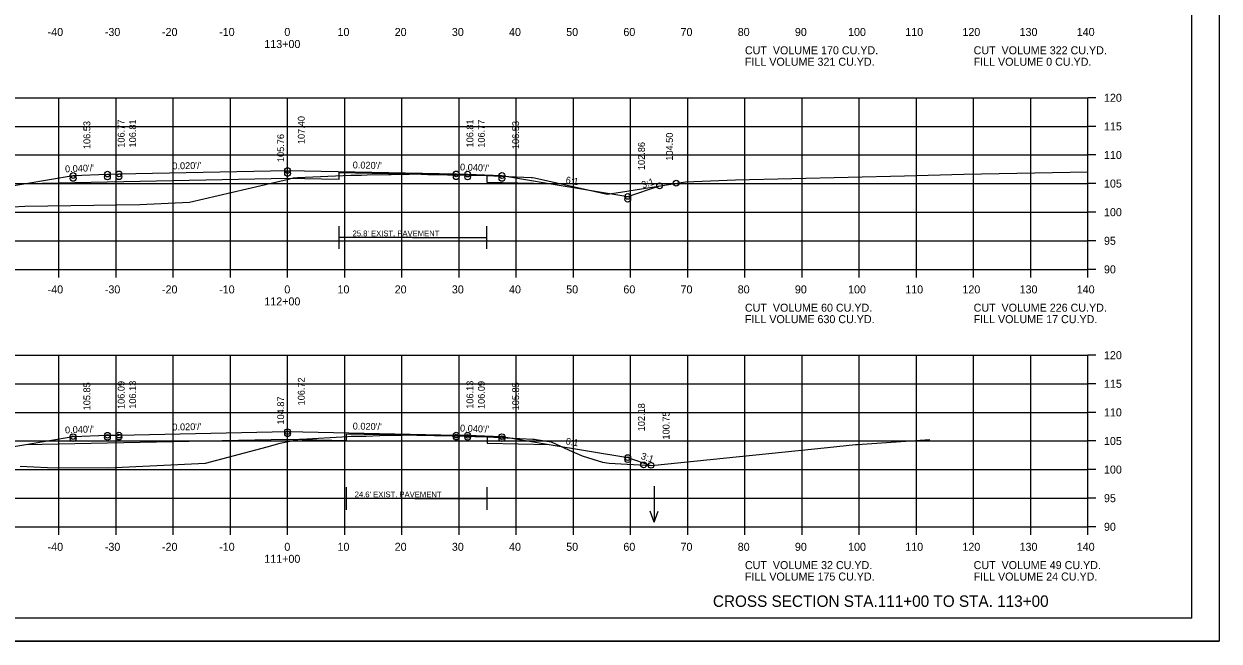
# Model space of a CAD drawing. Extents: x 1175611 to 1176402, y -433344 to -416213.
# Drawn here: x 1175734.9 to 1175943.9, y -432490.2 to -432382.3 of the extents above; entities that cross this region are included whole.
import ezdxf

# ---------------------------------------------------------------- set-up
doc = ezdxf.new("R2010")
doc.units = 0
for name, color, linetype in [('Default', 7, 'Continuous'), ('R_Alt Surface', 7, 'Continuous'), ('R_Axis', 7, 'Continuous'), ('R_Axis Annot', 7, 'Continuous'), ('R_Border', 7, 'Continuous'), ('R_Draft', 7, 'Continuous'), ('R_Exist Surface', 7, 'Continuous'), ('R_Fin Surface', 7, 'Continuous'), ('R_Grid', 7, 'Continuous'), ('R_No Plot', 7, 'Continuous'), ('R_Water Annot', 7, 'Continuous'), ('R_Xsect Elev', 7, 'Continuous'), ('R_Xsect Slope', 7, 'Continuous')]:
    doc.layers.add(name, color=color, linetype=linetype)

msp = doc.modelspace()

# ---------------------------------------------------------------- linework, layer by layer
at = {"layer": 'R_Alt Surface'}
for points in [[(1175735.2, -432410.17), (1175749.47, -432409.88), (1175780.97, -432409.25), (1175790.01, -432409.43), (1175790.01, -432408.26), (1175815.83, -432408.78), (1175815.83, -432409.95), (1175826.75, -432410.17)], [(1175735.2, -432455.81), (1175749.47, -432455.53), (1175780.97, -432454.9), (1175791.29, -432455.11), (1175791.29, -432453.94), (1175815.88, -432454.43), (1175815.88, -432455.6), (1175826.75, -432455.81)]]:
    msp.add_lwpolyline(points, dxfattribs=at)
at = {"layer": 'R_Axis'}
for p, q in [((1175920.97, -432425.2), (1175920.97, -432395.2)), ((1175922.37, -432395.2), (1175920.97, -432395.2)), ((1175922.37, -432400.2), (1175920.97, -432400.2)), ((1175922.37, -432405.2), (1175920.97, -432405.2)), ((1175922.37, -432410.2), (1175920.97, -432410.2)), ((1175922.37, -432415.2), (1175920.97, -432415.2)), ((1175922.37, -432420.2), (1175920.97, -432420.2)), ((1175640.97, -432425.2), (1175920.97, -432425.2)), ((1175740.97, -432426.6), (1175740.97, -432425.2)), ((1175750.97, -432426.6), (1175750.97, -432425.2)), ((1175760.97, -432426.6), (1175760.97, -432425.2)), ((1175770.97, -432426.6), (1175770.97, -432425.2)), ((1175780.97, -432426.6), (1175780.97, -432425.2)), ((1175790.97, -432426.6), (1175790.97, -432425.2)), ((1175800.97, -432426.6), (1175800.97, -432425.2)), ((1175810.97, -432426.6), (1175810.97, -432425.2)), ((1175820.97, -432426.6), (1175820.97, -432425.2)), ((1175830.97, -432426.6), (1175830.97, -432425.2)), ((1175840.97, -432426.6), (1175840.97, -432425.2)), ((1175850.97, -432426.6), (1175850.97, -432425.2)), ((1175860.97, -432426.6), (1175860.97, -432425.2)), ((1175870.97, -432426.6), (1175870.97, -432425.2)), ((1175880.97, -432426.6), (1175880.97, -432425.2)), ((1175890.97, -432426.6), (1175890.97, -432425.2)), ((1175900.97, -432426.6), (1175900.97, -432425.2)), ((1175910.97, -432426.6), (1175910.97, -432425.2)), ((1175920.97, -432426.6), (1175920.97, -432425.2)), ((1175922.37, -432425.2), (1175920.97, -432425.2)), ((1175920.97, -432470.2), (1175920.97, -432440.2)), ((1175922.37, -432440.2), (1175920.97, -432440.2)), ((1175922.37, -432445.2), (1175920.97, -432445.2)), ((1175922.37, -432450.2), (1175920.97, -432450.2)), ((1175922.37, -432455.2), (1175920.97, -432455.2)), ((1175922.37, -432460.2), (1175920.97, -432460.2)), ((1175922.37, -432465.2), (1175920.97, -432465.2)), ((1175640.97, -432470.2), (1175920.97, -432470.2)), ((1175740.97, -432471.6), (1175740.97, -432470.2)), ((1175750.97, -432471.6), (1175750.97, -432470.2)), ((1175760.97, -432471.6), (1175760.97, -432470.2)), ((1175770.97, -432471.6), (1175770.97, -432470.2)), ((1175780.97, -432471.6), (1175780.97, -432470.2)), ((1175790.97, -432471.6), (1175790.97, -432470.2)), ((1175800.97, -432471.6), (1175800.97, -432470.2)), ((1175810.97, -432471.6), (1175810.97, -432470.2)), ((1175820.97, -432471.6), (1175820.97, -432470.2)), ((1175830.97, -432471.6), (1175830.97, -432470.2)), ((1175840.97, -432471.6), (1175840.97, -432470.2)), ((1175850.97, -432471.6), (1175850.97, -432470.2)), ((1175860.97, -432471.6), (1175860.97, -432470.2)), ((1175870.97, -432471.6), (1175870.97, -432470.2)), ((1175880.97, -432471.6), (1175880.97, -432470.2)), ((1175890.97, -432471.6), (1175890.97, -432470.2)), ((1175900.97, -432471.6), (1175900.97, -432470.2)), ((1175910.97, -432471.6), (1175910.97, -432470.2)), ((1175920.97, -432471.6), (1175920.97, -432470.2)), ((1175922.37, -432470.2), (1175920.97, -432470.2))]:
    msp.add_line(p, q, dxfattribs=at)
at = {"layer": 'R_Border'}
for q in [(1175939.15, -432280.74), (1175622.97, -432486.2)]:
    msp.add_line((1175939.15, -432486.2), q, dxfattribs=at)
at = {"layer": 'R_Draft'}
for p, q in [((1175802.84, -432419.63), (1175790.01, -432419.63)), ((1175802.84, -432419.63), (1175815.83, -432419.63)), ((1175803.21, -432465.26), (1175791.29, -432465.26)), ((1175803.21, -432465.26), (1175815.88, -432465.26))]:
    msp.add_line(p, q, dxfattribs=at)
for points in [[(1175790.01, -432421.63), (1175790.01, -432417.63)], [(1175815.83, -432421.63), (1175815.83, -432417.63)], [(1175791.29, -432467.26), (1175791.29, -432463.26)], [(1175815.88, -432467.26), (1175815.88, -432463.26)]]:
    msp.add_lwpolyline(points, dxfattribs=at)
at = {"layer": 'R_Exist Surface'}
for points in [[(1175726.31, -432414.61), (1175735.01, -432414.16), (1175755.16, -432413.88), (1175763.8, -432413.44), (1175778.85, -432409.93), (1175781.12, -432409.4), (1175782.01, -432409.19), (1175782.3, -432409.18), (1175782.7, -432409.16), (1175792.03, -432408.75), (1175793.91, -432408.72), (1175794.87, -432408.7), (1175799.1, -432408.6), (1175801.01, -432408.56), (1175802.23, -432408.53), (1175802.82, -432408.52), (1175802.84, -432408.52), (1175803.01, -432408.52), (1175804.5, -432408.55), (1175804.95, -432408.56), (1175805.52, -432408.59), (1175807.42, -432408.63), (1175808.97, -432408.65), (1175813.17, -432408.72), (1175814.15, -432408.74), (1175814.43, -432408.75), (1175823.61, -432409.12), (1175823.74, -432409.12), (1175823.79, -432409.13), (1175823.83, -432409.13), (1175824.15, -432409.21), (1175836.9, -432412.07), (1175839.23, -432411.69), (1175850.58, -432409.87), (1175859.32, -432409.57), (1175888.87, -432408.86), (1175899.28, -432408.55), (1175920.97, -432408.15)], [(1175734.18, -432459.62), (1175738.98, -432459.84), (1175749.58, -432459.87), (1175766.61, -432459.08), (1175777.38, -432456.25), (1175779.66, -432455.61), (1175783.05, -432454.88), (1175783.11, -432454.87), (1175783.2, -432454.86), (1175783.29, -432454.86), (1175791.52, -432454.41), (1175792.1, -432454.38), (1175792.12, -432454.38), (1175792.17, -432454.38), (1175794.71, -432454.35), (1175797.05, -432454.26), (1175797.14, -432454.26), (1175800.85, -432454.2), (1175800.91, -432454.2), (1175800.95, -432454.2), (1175802.52, -432454.13), (1175802.53, -432454.13), (1175803.21, -432454.15), (1175803.25, -432454.15), (1175805.12, -432454.2), (1175805.14, -432454.21), (1175806.7, -432454.25), (1175806.78, -432454.25), (1175809.91, -432454.31), (1175810, -432454.31), (1175813.71, -432454.42), (1175813.74, -432454.42), (1175814.77, -432454.39), (1175823.88, -432454.87), (1175824, -432454.87), (1175824.12, -432454.88), (1175824.18, -432454.89), (1175824.44, -432454.93), (1175827.07, -432455.34), (1175830.22, -432456.78), (1175832.51, -432457.79), (1175834.37, -432458.4), (1175836.04, -432458.93), (1175837.24, -432459.08), (1175844.65, -432459.47), (1175875.44, -432456.33), (1175880.32, -432455.83), (1175880.65, -432455.83), (1175893.29, -432454.95)]]:
    msp.add_lwpolyline(points, dxfattribs=at)
at = {"layer": 'R_Fin Surface'}
for points in [[(1175713.01, -432415.27), (1175721.47, -432412.45), (1175735.2, -432410.17), (1175743.47, -432408.79), (1175749.47, -432408.55), (1175751.47, -432408.51), (1175780.97, -432407.92), (1175810.47, -432408.51), (1175812.47, -432408.55), (1175818.47, -432408.79), (1175826.75, -432410.17), (1175840.47, -432412.45), (1175846.05, -432410.59)], [(1175713.01, -432415.27), (1175721.47, -432412.45), (1175735.2, -432410.17), (1175743.47, -432408.79), (1175749.47, -432408.55), (1175751.47, -432408.51), (1175780.97, -432407.92), (1175810.47, -432408.51), (1175812.47, -432408.55), (1175818.47, -432408.79), (1175826.75, -432410.17), (1175840.47, -432412.45), (1175846.05, -432410.59)], [(1175704.27, -432458.46), (1175712.34, -432461.15), (1175721.47, -432458.1), (1175735.2, -432455.81), (1175743.47, -432454.44), (1175749.47, -432454.2), (1175751.47, -432454.16), (1175780.97, -432453.57), (1175810.47, -432454.16), (1175812.47, -432454.2), (1175818.47, -432454.44), (1175826.75, -432455.81), (1175840.47, -432458.1), (1175844.54, -432459.46)], [(1175704.27, -432458.46), (1175712.34, -432461.15), (1175721.47, -432458.1), (1175735.2, -432455.81), (1175743.47, -432454.44), (1175749.47, -432454.2), (1175751.47, -432454.16), (1175780.97, -432453.57), (1175810.47, -432454.16), (1175812.47, -432454.2), (1175818.47, -432454.44), (1175826.75, -432455.81), (1175840.47, -432458.1), (1175844.54, -432459.46)]]:
    msp.add_lwpolyline(points, dxfattribs=at)
at = {"layer": 'R_Grid'}
for p, q in [((1175640.97, -432395.2), (1175920.97, -432395.2)), ((1175740.97, -432425.2), (1175740.97, -432395.2)), ((1175750.97, -432425.2), (1175750.97, -432395.2)), ((1175760.97, -432425.2), (1175760.97, -432395.2)), ((1175770.97, -432425.2), (1175770.97, -432395.2)), ((1175780.97, -432425.2), (1175780.97, -432395.2)), ((1175790.97, -432425.2), (1175790.97, -432395.2)), ((1175800.97, -432425.2), (1175800.97, -432395.2)), ((1175810.97, -432425.2), (1175810.97, -432395.2)), ((1175820.97, -432425.2), (1175820.97, -432395.2)), ((1175830.97, -432425.2), (1175830.97, -432395.2)), ((1175840.97, -432425.2), (1175840.97, -432395.2)), ((1175850.97, -432425.2), (1175850.97, -432395.2)), ((1175860.97, -432425.2), (1175860.97, -432395.2)), ((1175870.97, -432425.2), (1175870.97, -432395.2)), ((1175880.97, -432425.2), (1175880.97, -432395.2)), ((1175890.97, -432425.2), (1175890.97, -432395.2)), ((1175900.97, -432425.2), (1175900.97, -432395.2)), ((1175910.97, -432425.2), (1175910.97, -432395.2)), ((1175920.97, -432425.2), (1175920.97, -432395.2)), ((1175640.97, -432400.2), (1175920.97, -432400.2)), ((1175640.97, -432405.2), (1175920.97, -432405.2)), ((1175640.97, -432410.2), (1175920.97, -432410.2)), ((1175640.97, -432415.2), (1175920.97, -432415.2)), ((1175640.97, -432420.2), (1175920.97, -432420.2)), ((1175640.97, -432425.2), (1175920.97, -432425.2)), ((1175640.97, -432440.2), (1175920.97, -432440.2)), ((1175740.97, -432470.2), (1175740.97, -432440.2)), ((1175750.97, -432470.2), (1175750.97, -432440.2)), ((1175760.97, -432470.2), (1175760.97, -432440.2)), ((1175770.97, -432470.2), (1175770.97, -432440.2)), ((1175780.97, -432470.2), (1175780.97, -432440.2)), ((1175790.97, -432470.2), (1175790.97, -432440.2)), ((1175800.97, -432470.2), (1175800.97, -432440.2)), ((1175810.97, -432470.2), (1175810.97, -432440.2)), ((1175820.97, -432470.2), (1175820.97, -432440.2)), ((1175830.97, -432470.2), (1175830.97, -432440.2)), ((1175840.97, -432470.2), (1175840.97, -432440.2)), ((1175850.97, -432470.2), (1175850.97, -432440.2)), ((1175860.97, -432470.2), (1175860.97, -432440.2)), ((1175870.97, -432470.2), (1175870.97, -432440.2)), ((1175880.97, -432470.2), (1175880.97, -432440.2)), ((1175890.97, -432470.2), (1175890.97, -432440.2)), ((1175900.97, -432470.2), (1175900.97, -432440.2)), ((1175910.97, -432470.2), (1175910.97, -432440.2)), ((1175920.97, -432470.2), (1175920.97, -432440.2)), ((1175640.97, -432445.2), (1175920.97, -432445.2)), ((1175640.97, -432450.2), (1175920.97, -432450.2)), ((1175640.97, -432455.2), (1175920.97, -432455.2)), ((1175640.97, -432460.2), (1175920.97, -432460.2)), ((1175640.97, -432465.2), (1175920.97, -432465.2)), ((1175640.97, -432470.2), (1175920.97, -432470.2))]:
    msp.add_line(p, q, dxfattribs=at)
at = {"layer": 'R_No Plot'}
msp.add_line((1175610.57, -432490.18), (1175943.91, -432490.18), dxfattribs=at)
msp.add_lwpolyline([(1175610.57, -432276.84), (1175943.91, -432276.84), (1175943.91, -432490.18), (1175610.57, -432490.18)], close=True, dxfattribs=at)
for centre in [(1175743.47, -432408.79), (1175749.47, -432408.55), (1175751.47, -432408.51), (1175780.97, -432407.92), (1175780.97, -432408.42), (1175810.47, -432408.51), (1175812.47, -432408.55), (1175818.47, -432408.79), (1175743.47, -432409.29), (1175749.47, -432409.05), (1175751.47, -432409.01), (1175810.47, -432409.01), (1175812.47, -432409.05), (1175818.47, -432409.29), (1175846.05, -432410.59), (1175846.05, -432410.59), (1175848.94, -432410.13), (1175840.47, -432412.45), (1175840.47, -432412.95), (1175743.47, -432454.44), (1175749.47, -432454.2), (1175749.47, -432454.56), (1175751.47, -432454.16), (1175751.47, -432454.52), (1175780.97, -432453.57), (1175780.97, -432453.93), (1175810.47, -432454.16), (1175810.47, -432454.52), (1175812.47, -432454.2), (1175812.47, -432454.56), (1175818.47, -432454.44), (1175743.47, -432454.8), (1175818.47, -432454.8), (1175840.47, -432458.1), (1175840.47, -432458.47), (1175843.24, -432459.39), (1175844.54, -432459.46), (1175844.54, -432459.46)]:
    msp.add_circle(centre, 0.5, dxfattribs=at)
at = {"layer": 'R_Water Annot'}
for p, q in [((1175845.07, -432463.09), (1175845.07, -432469.37)), ((1175845.07, -432469.37), (1175844.37, -432467.45)), ((1175845.07, -432469.37), (1175845.77, -432467.45))]:
    msp.add_line(p, q, dxfattribs=at)

# ---------------------------------------------------------------- texts
at = {"layer": 'Default'}
for s, p in [('CUT  VOLUME 170 CU.YD.', (1175860.97, -432387.6)), ('CUT  VOLUME 322 CU.YD.', (1175900.97, -432387.6)), ('FILL VOLUME 321 CU.YD.', (1175860.97, -432389.6)), ('FILL VOLUME 0 CU.YD.', (1175900.97, -432389.6)), ('CUT  VOLUME 60 CU.YD.', (1175860.97, -432432.6)), ('CUT  VOLUME 226 CU.YD.', (1175900.97, -432432.6)), ('FILL VOLUME 630 CU.YD.', (1175860.97, -432434.6)), ('FILL VOLUME 17 CU.YD.', (1175900.97, -432434.6)), ('CUT  VOLUME 32 CU.YD.', (1175860.97, -432477.6)), ('CUT  VOLUME 49 CU.YD.', (1175900.97, -432477.6)), ('FILL VOLUME 175 CU.YD.', (1175860.97, -432479.6)), ('FILL VOLUME 24 CU.YD.', (1175900.97, -432479.6))]:
    msp.add_text(s, height=1.4, dxfattribs=at).set_placement(p)
at = {"layer": 'R_Axis Annot'}
for s, p in [('-40', (1175739.01, -432384.4)), ('-30', (1175749.01, -432384.4)), ('-20', (1175759.01, -432384.4)), ('-10', (1175769.01, -432384.4)), ('0', (1175780.41, -432384.4)), ('10', (1175789.71, -432384.4)), ('20', (1175799.71, -432384.4)), ('30', (1175809.71, -432384.4)), ('40', (1175819.71, -432384.4)), ('50', (1175829.71, -432384.4)), ('60', (1175839.71, -432384.4)), ('70', (1175849.71, -432384.4)), ('80', (1175859.71, -432384.4)), ('90', (1175869.71, -432384.4)), ('100', (1175879.01, -432384.4)), ('110', (1175889.01, -432384.4)), ('120', (1175899.01, -432384.4)), ('130', (1175909.01, -432384.4)), ('140', (1175919.01, -432384.4)), ('113+00', (1175776.91, -432386.5)), ('120', (1175923.77, -432395.9)), ('115', (1175923.77, -432400.9)), ('110', (1175923.77, -432405.9)), ('105', (1175923.77, -432410.9)), ('100', (1175923.77, -432415.9)), ('95', (1175923.77, -432420.9)), ('90', (1175923.77, -432425.9)), ('-40', (1175739.01, -432429.4)), ('-30', (1175749.01, -432429.4)), ('-20', (1175759.01, -432429.4)), ('-10', (1175769.01, -432429.4)), ('0', (1175780.41, -432429.4)), ('10', (1175789.71, -432429.4)), ('20', (1175799.71, -432429.4)), ('30', (1175809.71, -432429.4)), ('40', (1175819.71, -432429.4)), ('50', (1175829.71, -432429.4)), ('60', (1175839.71, -432429.4)), ('70', (1175849.71, -432429.4)), ('80', (1175859.71, -432429.4)), ('90', (1175869.71, -432429.4)), ('100', (1175879.01, -432429.4)), ('110', (1175889.01, -432429.4)), ('120', (1175899.01, -432429.4)), ('130', (1175909.01, -432429.4)), ('140', (1175919.01, -432429.4)), ('112+00', (1175776.91, -432431.5)), ('120', (1175923.77, -432440.9)), ('115', (1175923.77, -432445.9)), ('110', (1175923.77, -432450.9)), ('105', (1175923.77, -432455.9)), ('100', (1175923.77, -432460.9)), ('95', (1175923.77, -432465.9)), ('90', (1175923.77, -432470.9)), ('-40', (1175739.01, -432474.4)), ('-30', (1175749.01, -432474.4)), ('-20', (1175759.01, -432474.4)), ('-10', (1175769.01, -432474.4)), ('0', (1175780.41, -432474.4)), ('10', (1175789.71, -432474.4)), ('20', (1175799.71, -432474.4)), ('30', (1175809.71, -432474.4)), ('40', (1175819.71, -432474.4)), ('50', (1175829.71, -432474.4)), ('60', (1175839.71, -432474.4)), ('70', (1175849.71, -432474.4)), ('80', (1175859.71, -432474.4)), ('90', (1175869.71, -432474.4)), ('100', (1175879.01, -432474.4)), ('110', (1175889.01, -432474.4)), ('120', (1175899.01, -432474.4)), ('130', (1175909.01, -432474.4)), ('140', (1175919.01, -432474.4)), ('111+00', (1175776.91, -432476.5))]:
    msp.add_text(s, height=1.4, dxfattribs=at).set_placement(p)
at = {"layer": 'R_Draft'}
for s, height, p in [("25.8' EXIST. PAVEMENT", 1, (1175792.34, -432419.41)), ("24.6' EXIST. PAVEMENT", 1, (1175792.71, -432465.04)), ('CROSS SECTION STA.111+00 TO STA. 113+00', 2, (1175855.37, -432484.2))]:
    msp.add_text(s, height=height, dxfattribs=at).set_placement(p)
at = {"layer": 'R_Xsect Elev'}
for s, p in [('106.53', (1175746.47, -432404.17)), ('106.77', (1175752.47, -432403.93)), ('106.81', (1175754.47, -432403.89)), ('107.40', (1175783.97, -432403.3)), ('106.81', (1175813.47, -432403.89)), ('106.77', (1175815.47, -432403.93)), ('106.53', (1175821.47, -432404.17)), ('105.76', (1175780.37, -432406.44)), ('104.50', (1175848.37, -432406.2)), ('102.86', (1175843.47, -432407.84)), ('105.85', (1175746.47, -432449.85)), ('106.09', (1175752.47, -432449.61)), ('106.13', (1175754.47, -432449.57)), ('106.72', (1175783.97, -432448.98)), ('106.13', (1175813.47, -432449.57)), ('106.09', (1175815.47, -432449.61)), ('105.85', (1175821.47, -432449.85)), ('104.87', (1175780.37, -432452.33)), ('102.18', (1175843.47, -432453.51)), ('100.75', (1175847.78, -432454.95))]:
    msp.add_text(s, height=1.2, rotation=90, dxfattribs=at).set_placement(p)
at = {"layer": 'R_Xsect Slope'}
for s, rotation, p in [("0.040'/'", 2.2906, (1175742.07, -432408.24)), ("0.020'/'", 1.1458, (1175760.83, -432407.72)), ("0.020'/'", 358.8542, (1175792.36, -432407.54)), ("0.040'/'", 357.7094, (1175811.12, -432407.89)), ('6:1', 350.5377, (1175829.55, -432410.13)), ('3:1', 18.4349, (1175843.1, -432411.05)), ("0.020'/'", 1.1458, (1175760.83, -432453.37)), ("0.020'/'", 358.8542, (1175792.36, -432453.19)), ("0.040'/'", 2.2906, (1175742.07, -432453.89)), ("0.040'/'", 357.7094, (1175811.12, -432453.54)), ('6:1', 350.5377, (1175829.55, -432455.78)), ('3:1', 341.5651, (1175842.67, -432458.31))]:
    msp.add_text(s, height=1.2, rotation=rotation, dxfattribs=at).set_placement(p)

doc.saveas('drawing.dxf')
